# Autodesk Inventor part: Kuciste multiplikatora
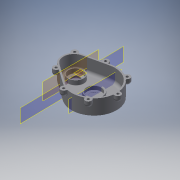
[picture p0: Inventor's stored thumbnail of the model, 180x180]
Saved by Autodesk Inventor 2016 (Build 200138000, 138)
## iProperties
Created: 2015-08
Part Number: Kuciste multiplikatora
Material: Generic
Document SubType Name: Modeling
Designer: Ugljesa
Density: 1 g/cm^3
Appearance: Default
Mass: 294.301 g
Surface Area: 1107.82 cm^2
Volume: 294.301 cm^3
Author: Ugljesa
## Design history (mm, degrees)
workplane "Work Plane1"
workplane "Work Plane2"
sketch "Sketch1"
  geometry: L1 (-47.068, -29.002)-(21.331, -71.381); L2 (-32.335, 44.495)-(47.113, 57.239); L3 (47.905, 52.302)-(-31.543, 39.558); L4 (-44.434, -24.752)-(23.965, -67.131); L5 (-31.543, 39.558)-(-35.338, -22.776); C1 r 7.5 at (-20, 5) reference; C2 r 10 at (58.199, -11.877) reference; A1 r 70 centre (58.199, -11.877) between (21.331, -71.381) and (47.113, 57.239); A2 r 65 centre (58.199, -11.877) between (23.965, -67.131) and (47.905, 52.302); A3 r 35 centre (-26, 5) between (-31.543, 39.558) and (-44.434, -24.752); A4 r 40 centre (-26, 5) between (-32.335, 44.495) and (-47.068, -29.002); 1 further point
  constraints: 10 end point, 9 point on circle, 6 centre point, 6 tangent, 1 concentric, 1 horizontal alignment, 5 other
  dimensions: "d3" = 70 radius of A1; "d6" = 5 radial gap between concentric circles of A1 A2; "d25" = 5 distance between parallel lines of L2 L3; "d105" = 5 radial gap between concentric circles of A4 A3; "d106" = 6 distance of C1.centre A3.centre; "d109" = 40 radius of A4
extrude "Extrusion11" new body sketch "Sketch1" distance "d110" = 35; taper "d111" = 0 deg; dims "d176" = 15, "d177" = 0
workplane "Work Plane7"
sketch "Sketch5"
  geometry: L1 (10.103, 51.176)-(-3.475, 46.891); L2 (-52.052, -37.533)-(-64.019, -37.533); L3 (-49.877, 49.276)-(-62.496, 49.276); L4 (127.481, -1.877)-(132.481, -1.877); L5 (127.481, -21.877)-(132.481, -21.877); L6 (127.481, -1.877)-(127.481, -21.877); C1 r 9 at (58.199, -11.877); A1 r 75 centre (53.151, -11.877) between (36.64, 61.283) and (9.719, -73.022); A2 r 10 centre (132.481, -11.877) between (132.481, -21.877) and (132.481, -1.877); A3 r 70 centre (58.199, -11.877) between (17.663, -68.945) and (42.789, 56.405) reference; 1 further point
  constraints: 12 end point, 10 point on circle, 4 centre point, 2 horizontal, 2 perpendicular, 2 tangent, 1 vertical, 4 other
  dimensions: "d29" = 10 radius of A2; "d153" = 5 distance from line of L6 A2.centre
extrude "Extrusion6" join sketch "Sketch5" distance "d32" = 20; taper "d33" = 0 deg
workplane "Work Plane3"
workplane "Work Plane23"
revolve "Revolution1" stored, may be unused: angle "d79" = 90 deg
chamfer "Chamfer2" distance "d82" = 0.5; stored, may be unused: second distance "d83" = 2, angle "d84" = 45 deg
sketch "Sketch11"
  geometry: C1 r 13 at (0, 0); 1 further point
  constraints: 1 centre point
extrude "Extrusion9" cut sketch "Sketch11" distance "d85" = 39; taper "d86" = 0 deg
workplane "Work Plane4"
sketch "Sketch13"
  geometry: L1 (0, 0)-(57.224, 0) reference; L2 (4, 12.5)-(12, 12.5) reference; L3 (4, -12.5)-(12, -12.5) reference; L4 (-0.5, 14)-(0.5, 14); L5 (0.5, 14)-(0.5, 15); L6 (0.5, 15)-(-0.5, 15); L7 (0, 23.5)-(12.5, 23.5); L8 (12.5, 23.5)-(12.5, 28.5); L9 (12.5, 28.5)-(-0.5, 28.5); L10 (-0.5, 28.5)-(-0.5, 14); L11 (0, 23.5)-(0, 15); L12 (5.5, -11.5)-(5.5, 11.5) reference; L13 (0.5, -6.022)-(0.5, 39.778) reference; 1 further point
  constraints: 22 end point, 6 perpendicular, 4 horizontal, 1 collinear, 1 midpoint, 1 point on line, 1 vertical, 4 other
  dimensions: "d90" = 28 diameter of L4 L1; "d91" = 1 distance of L5.end L6.end; "d92" = 1 distance between parallel lines of L4 L6; "d93" = 47 diameter of L7 L1; "d94" = 5 distance between parallel lines of L7 L9; "d95" = 13 distance between parallel lines of L10 L8
revolve "Revolution2" sketch "Sketch13" stored, may be unused: angle "d97" = 90 deg
fillet "Fillet13" dims "d116" = 10
fillet "Fillet14" dims "d117" = 1
sketch "Sketch18"
  geometry: L1 (-21.331, -71.381)-(47.068, -29.002) reference; L2 (32.335, 44.495)-(-47.113, 57.239) reference; A1 r 40 centre (26, 5) between (47.068, -29.002) and (32.335, 44.495) reference; A2 r 70 centre (-58.199, -11.877) between (-47.113, 57.239) and (-21.331, -71.381) reference
extrude "Extrusion14" join sketch "Sketch18" distance "d122" = 5; taper "d123" = 0 deg
sketch "Sketch19"
  geometry: A1 r 10 centre (132.481, -11.877) between (132.481, -1.877) and (132.481, -21.877) reference; 1 further point
hole "Hole3" sketch "Sketch19" at (132.481, -11.877) diameter "d124" = 8; stored, may be unused: countersink angle "d128" = 90 deg, drill point angle "d130" = 120 deg; dims "d125" = 6, "d126" = 1, "d127" = 2, "d129" = 15
pattern_circular "Circular Pattern3" dims "d132" = 110 deg
pattern_circular "Circular Pattern4" dims "d135" = -55 deg
sketch "Sketch21"
  geometry: L1 (17.034, 52.414)-(36.781, 55.582); L2 (36.781, 55.582)-(35.989, 60.519); L3 (16.242, 57.351)-(17.034, 52.414); L4 (-46.315, 39.457)-(-60.457, 25.315); L5 (-60.457, 25.315)-(-63.993, 28.851); L6 (-49.851, 42.993)-(-46.315, 39.457); L7 (-26, 5)-(-56.922, 35.922); L8 (-27.516, -41.116)-(-30.15, -45.366); L9 (-44.517, -30.582)-(-27.516, -41.116); L10 (-47.151, -34.833)-(-44.517, -30.582); L11 (47.113, 57.239)-(-32.335, 44.495) reference; L12 (-26, 5)-(-26, 130.742); L13 (-47.068, -29.002)-(21.331, -71.381) reference; A1 r 10 centre (26.115, 58.935) between (35.989, 60.519) and (16.242, 57.351); A2 r 10 centre (-56.922, 35.922) between (-49.851, 42.993) and (-63.993, 28.851); A3 r 10 centre (-38.65, -40.099) between (-47.151, -34.833) and (-30.15, -45.366); A4 r 40 centre (-26, 5) between (-60.025, 26.031) and (-49.164, -27.61) reference; 1 further point
  constraints: 22 end point, 10 point on circle, 6 tangent, 5 perpendicular, 4 centre point, 2 collinear, 1 coincident, 1 parallel, 1 vertical, 4 other
  dimensions: "d137" = 10 radius of A1; "d140" = 50 distance from line of L7.start L3; "d141" = 10 radius of A2; "d142" = 5 distance from line of L4 L7.end; "d145" = 10 radius of A3; "d147" = 5 distance from line of L9 A3.centre; "d148" = 3 distance from line of L7.start L10; "d178" = 5 distance from line of L11 A1.centre; "d179" = 45 deg angle of L12 L7
extrude "Extrusion15" join sketch "Sketch21" distance "d149" = 20; taper "d150" = 0 deg
fillet "Fillet15" dims "d151" = 10
sketch "Sketch22"
  geometry: A1 r 10 centre (26.115, 58.935) between (35.989, 60.519) and (16.242, 57.351) reference; A2 r 10 centre (-56.922, 35.922) between (-63.993, 28.851) and (-49.851, 42.993) reference; A3 r 10 centre (-38.65, -40.099) between (-47.151, -34.833) and (-30.15, -45.366) reference; 1 further point
hole "Hole4" sketch "Sketch22" at (26.115, 58.935), (-56.922, 35.922), (-38.65, -40.099) diameter "d154" = 8; stored, may be unused: countersink angle "d158" = 90 deg, drill point angle "d160" = 120 deg; dims "d155" = 6, "d156" = 1, "d157" = 2, "d159" = 15
fillet "Fillet16" dims "d161" = 10
chamfer "Chamfer3" distance "d166" = 1; stored, may be unused: second distance "d167" = 2, angle "d168" = 45 deg
fillet "Fillet18" dims "d169" = 1
sketch "Sketch24"
  geometry: C1 r 12 at (-20, 5) reference; C2 r 13 at (-20, 5); 1 further point
  constraints: 1 centre point, 1 coincident
  dimensions: "d170" = 26 diameter of C2
extrude "Extrusion17" cut sketch "Sketch24" stored distance "d171" = 1; taper "d172" = 0 deg
fillet "Fillet19" dims "d173" = 1
body "Solid1"
sketch "Sketch10"
  geometry: L1 (-12.5, 12)-(-12.5, -6) reference; L2 (12.5, 12)-(12.5, -6) reference; L3 (-13, -29)-(-13, -35); L4 (-14, -29)-(-14, -35); L5 (-23.5, -35)-(-23.5, -15); L6 (-23.5, -15)-(-26, -15); L7 (-26, -15)-(-26, -35); L8 (0, 0)-(0, 15.071) reference; L9 (-26, -35)-(-23.5, -35); L10 (-13, -29)-(-14, -29); L11 (-13, -35)-(-14, -35); L12 (-34.002, -35)-(39.495, -35) reference; 4 further points; 1 other entity
  constraints: 22 end point, 6 vertical, 2 perpendicular, 1 collinear, 1 horizontal, 1 point on line, 9 other
  dimensions: "d73" = 26 diameter of L3 L8; "d74" = 28 diameter of L4 L8; "d77" = 47 diameter of L5 L8; "d78" = 52 diameter of L7 L8; "d174" = 6 distance of L4.start L4.end; "d175" = 20 distance of L6.end L7.end
node "Reference6"
node "Reference8"
